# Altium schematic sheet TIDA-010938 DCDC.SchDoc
size 431 x 279 mm; Date: Not shown in title block; ApprovedBy: Not shown in title block; CheckedBy: Not shown in title block; Author: Not shown in title block; CompanyName: Not shown in title block; Engineer: Not shown in title block; Organization: Not shown in title block; Address1: Not shown in title block; Address2: Not shown in title block; Address3: Not shown in title block; Address4: Not shown in title block; DocumentNumber: 1; Revision: Use project parameter SCH_Rev; SheetNumber: 1; SheetTotal: 9; PageSetup: Record=PageOptions¦CenterHorizontal=True¦CenterVertical=True¦PrintScale=1.00¦XCorrection=1.00¦YCorrection=1.00¦PrintKind=0¦BorderSize=5000000¦LeftOffset=0¦BottomOffset=0¦Orientation=2¦PaperLength=1000¦PaperWidth=1000¦Scale=100¦PaperSource=15¦PrintQuality=600¦MediaType=1¦DitherType=10¦PaperKind=Letter¦PrintScaleMode=1
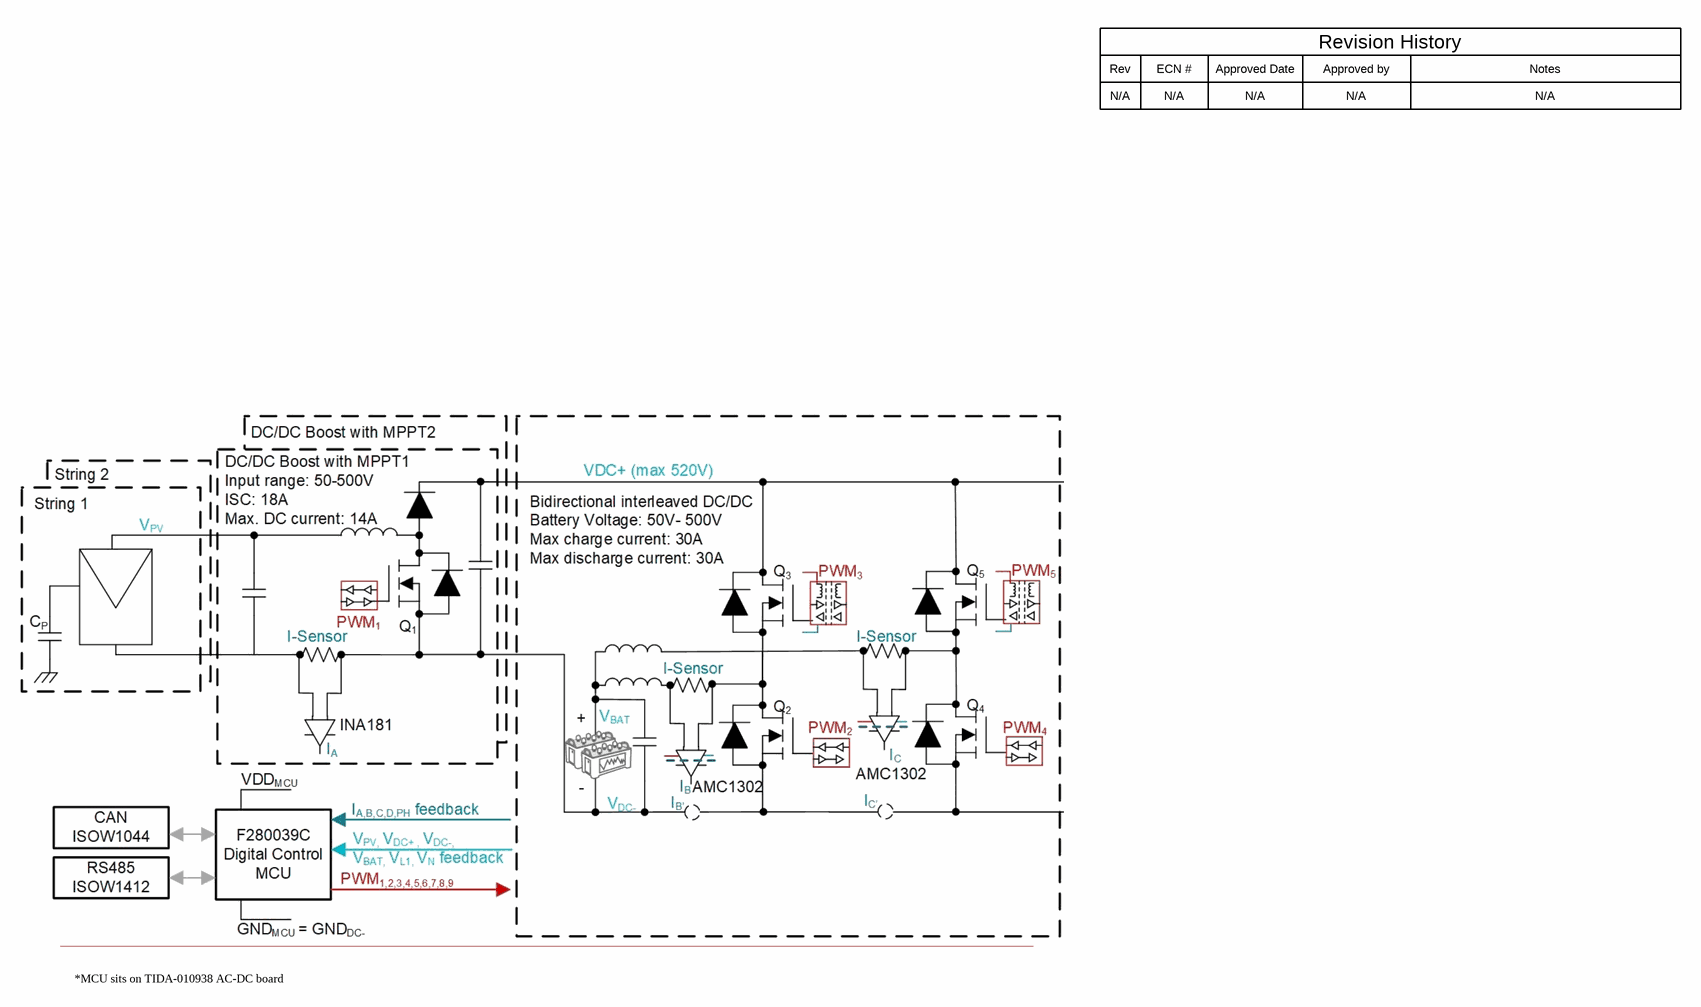
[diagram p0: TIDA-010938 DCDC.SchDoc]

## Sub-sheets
Designator = TIDA-010938 DCDC_Top.SchDoc: no entries

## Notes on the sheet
- Rev
- N/A
- ECN #
- Approved Date
- Approved by
- Revision History
- Notes
- *MCU sits on TIDA-010938 AC-DC board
